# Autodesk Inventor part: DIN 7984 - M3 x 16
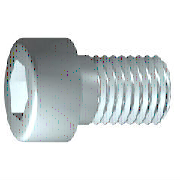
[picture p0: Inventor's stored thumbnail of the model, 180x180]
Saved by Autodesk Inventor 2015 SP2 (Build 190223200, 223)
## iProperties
Created: 2012-02
Part Number: DIN 7984 - M3 x 16
Material: Stahl, weich
Description: Zylinderkopfschraube
Document SubType Name: Modeling
Standard: DIN 7984
Designer: rYan
Standard Revision: 1985
Standards Organization: DIN
Language: de-DE
Size Designation: M3 x 16
Categories: <MemberInstance><Categories><Category DisplayName="Verbindungselemente" InternalName="e4da775c-781d-43d5-af7c-5136215cf5a6" Mnemonic="FSTN"><Category DisplayNam
Density: 7.85 g/cm^3
Mass: 1.20728 g
Surface Area: 2.39725 cm^2
Volume: 0.153794 cm^3
Appearance: Halbpoliert
IsCustomPart: 0
Author: rYan
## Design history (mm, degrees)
sketch "Skizze1"
  geometry: L1 (0.167, 0)-(16, 0); L2 (16, 0)-(16, 1.5); L3 (16, 1.5)-(1.5, 1.5); L4 (1.5, 1.5)-(1.193, 1.5); L5 (1.193, 1.5)-(0, 1.5); L6 (0, 1.5)-(0, 2.75); L7 (0, 2.75)-(-2, 2.75); L8 (-2, 2.75)-(-2, 1.155); L9 (-2, 1.155)-(-0.5, 1.155); L10 (-0.5, 1.155)-(0.167, 0); L11 (-5.6, 0)-(19.6, 0) reference; L12 (0, -0.55)-(0, 3.3) reference; L13 (1.5, 1.5)-(0, 1.5)
  constraints: 22 end point, 6 parallel, 2 collinear, 2 perpendicular, 1 horizontal, 1 point on line
  dimensions: "d1" = 14.5 distance from line of L3.end L2 (= GEL); "d2" = 0.30683 distance of L4.end L3.end (computed from GAL); "d3" = 2 distance between parallel lines of L8 L6 (= KOH); "d4" = 1.5 distance of L8.end L9.end (= INTI); "d5" = 60 deg angle of L10 L1; "d6" = 3 diameter of L3 L1 (= GD); "d7" = 3 diameter of L5 L1 (= BDM); "d8" = 2.3094 diameter of L9 L1 (= 1.1547 x SW); "d9" = 5.5 diameter of L7 L1 (= KOD); "d26" = 16 distance between parallel lines of L12 L2 (= NLG)
revolve "Körper" sketch "Skizze1" stored, may be unused: angle "d10" = 90 deg
sketch "Skizze2"
  geometry: L1 (0, -3.85)-(0, 3.85) reference; L2 (-3.85, 0)-(3.85, 0) reference; L3 (1.155, 0)-(0.577, -1); L4 (0.577, -1)-(-0.577, -1); L5 (-0.577, -1)-(-1.155, 0); L6 (-1.155, 0)-(-0.577, 1); L7 (-0.577, 1)-(0.577, 1); L8 (0.577, 1)-(1.155, 0); 2 further points
  constraints: 12 end point, 1 coincident, 1 horizontal alignment, 1 point on line, 12 other
extrude "Loch" join sketch "Skizze2" stored distance "d11" = 10; taper "d12" = 0 deg
workplane "Work Plane1"
fillet "Fillet2" dims "d30" = 0.1 (= R)
body "Solid1"
fillet "Rundung1" dims "d17" = 0.3 (= RR)
feature "Gewinde" dims "d13" = 14.5 (= GEL), "d14" = 0
chamfer "Fase1" distance "d15" = 0.30673 (= -0.5 x SPD + 0.5 x GD); stored, may be unused: second distance "d16" = 0.30673 (= GUL), angle "d27" = 45 deg
other parameters: "GD" = 3 (= NND) [user parameter; used in 2 equation terms], "NLG" = 16 [user parameter; used in 1 equation term], "GEL" = 14.5 [user parameter; used in 2 equation terms], "KOD" = 5.5 [user parameter; used in 1 equation term], "KOH" = 2 [user parameter; used in 1 equation term], "INTI" = 1.5 [user parameter; used in 1 equation term], "GAL" = 0.30673 (= 0.61345 x PTC) [user parameter; used in 1 equation term], "GUL" = 0.30673 (= 0.61345 x PTC) [user parameter; used in 1 equation term], "BDM" = 3 (= NND) [user parameter; used in 1 equation term], "SW" = 2 [user parameter; used in 2 equation terms], "RR" = 0.3 [user parameter; used in 1 equation term], "SPD" = 2.38655 (= NND - 1.2269 x PTC) [user parameter; used in 1 equation term], "d19" = 0, "d28" = 0, "d29" = 0, "R" = 0.1 [user parameter; used in 1 equation term], "TOA" = 30 deg [user parameter], "GD1" = 2.38655 (= THREADDIA - 1.2269 x PTC) [user parameter], "THREADDIA" = 3 [user parameter; used in 1 equation term], "FAWI" = 45 deg [user parameter], "ANG" = 120 deg [user parameter], "PTC" = 0.5 [user parameter; used in 5 equation terms], "NND" = 3 [user parameter; used in 3 equation terms], "E0" = 2.31 (= 1.155 x SW) [user parameter]
